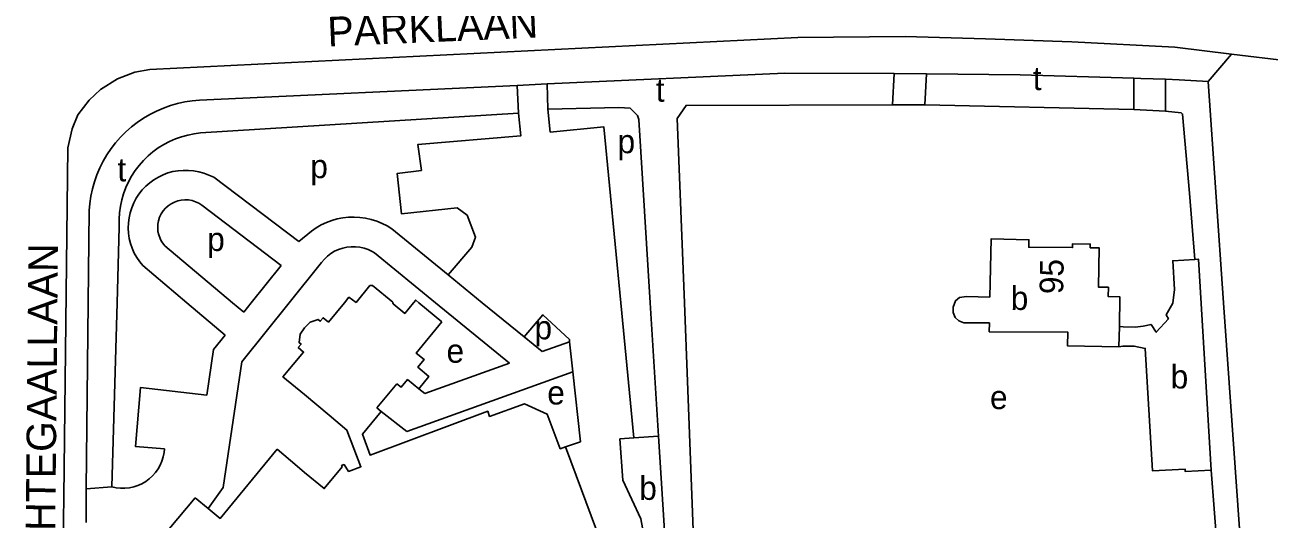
# Model space of a CAD drawing. Extents: x 161775 to 163181, y 382878 to 383925.
# Drawn here: x 161952.7 to 162163.3, y 383537.4 to 383621.1 of the extents above; entities that cross this region are included whole.
import ezdxf

# ---------------------------------------------------------------- set-up
doc = ezdxf.new("R2010")
doc.units = 0
for name, color, linetype in [('BLT_Basislijn', 7, 'Continuous'), ('BLT_Bebouwing', 7, 'Continuous'), ('BLT_Centroide', 7, 'Continuous'), ('BLT_Huisnummer', 7, 'Continuous'), ('BLT_Onderverdeling_panden', 7, 'Continuous'), ('BLT_Straatnaam', 7, 'Continuous')]:
    doc.layers.add(name, color=color, linetype=linetype)

msp = doc.modelspace()

# ---------------------------------------------------------------- linework, layer by layer
at = {"layer": 'BLT_Basislijn'}
for p, q in [((162147.39, 383617.3), (162156.96, 383616.15)), ((162153.03, 383611.52), (162156.96, 383616.15)), ((162099.86, 383612.83), (162099.6, 383607.57)), ((162099.86, 383612.83), (162105.35, 383612.82)), ((162105.02, 383607.53), (162105.35, 383612.82)), ((162140.43, 383612.06), (162140.43, 383606.73)), ((162141.64, 383612.02), (162140.43, 383612.06)), ((162145.81, 383611.88), (162141.64, 383612.02)), ((162145.78, 383606.45), (162145.81, 383611.88)), ((162148.09, 383611.77), (162145.81, 383611.88)), ((162153.03, 383611.52), (162148.09, 383611.77)), ((162036.05, 383610.83), (161982.25, 383608.35)), ((162036.05, 383610.83), (162041.08, 383611.08)), ((162036.24, 383606.12), (162036.05, 383610.83)), ((162041.2, 383606.79), (162041.08, 383611.08)), ((162155.64, 383574.02), (162153.03, 383611.52)), ((162099.6, 383607.57), (162105.02, 383607.53)), ((162140.43, 383606.73), (162105.02, 383607.53)), ((162036.24, 383606.12), (161982.41, 383602.78)), ((162145.78, 383606.45), (162140.43, 383606.73)), ((161984.64, 383595.29), (161999.05, 383584.38)), ((161963.54, 383589.62), (161963.38, 383574.02)), ((161982.62, 383590.54), (161996.09, 383580.35)), ((161968.65, 383586.84), (161968.28, 383574.02)), ((162014.8, 383586.52), (162024.32, 383578.75)), ((161976.36, 383583.66), (161987.85, 383574.02)), ((162011.87, 383582.48), (162022.22, 383574.02)), ((161972.64, 383580.32), (161980.11, 383574.02)), ((161991, 383574.02), (161996.09, 383580.35)), ((162024.32, 383578.75), (162030.11, 383574.02)), ((161963.38, 383574.02), (161963.03, 383542.53)), ((161968.28, 383574.02), (161967.39, 383542.85)), ((161980.11, 383574.02), (161986.6, 383568.55)), ((161987.85, 383574.02), (161989.73, 383572.44)), ((161989.73, 383572.44), (161991, 383574.02)), ((162022.22, 383574.02), (162034.74, 383563.79)), ((162030.11, 383574.02), (162037.19, 383568.24)), ((162161.28, 383493.04), (162155.64, 383574.02)), ((162037.19, 383568.24), (162040.24, 383565.75)), ((162040.24, 383565.75), (162044.91, 383567.43)), ((162044.91, 383567.43), (162045.45, 383562.31)), ((162020.41, 383558.65), (162034.74, 383563.79)), ((162017.32, 383552.23), (162045.45, 383562.31)), ((162019.36, 383559.43), (162020.41, 383558.65)), ((162012.99, 383555.61), (162017.32, 383552.23)), ((162153.52, 383545.68), (162156.18, 383511.56)), ((161963.03, 383542.53), (161963.02, 383536.82)), ((161967.39, 383542.85), (161963.03, 383542.53)), ((161983.68, 383539.17), (161986.22, 383542.73))]:
    msp.add_line(p, q, dxfattribs=at)
for points in [[(161973.85, 383613.54), (162083.56, 383618.94), (162101.7, 383619.1), (162115.33, 383618.75), (162129.91, 383618.23), (162147.39, 383617.3)], [(162156.96, 383616.15), (162166.39, 383615.01), (162177.92, 383614.05)], [(161959.97, 383600.25), (161960.67, 383603.5), (161961.63, 383605.86), (161963.55, 383608.36), (161965.5, 383610.15), (161968.34, 383611.93), (161971.29, 383613.05), (161973.85, 383613.54)], [(162099.86, 383612.83), (162081.33, 383612.9), (162041.08, 383611.08)], [(162105.35, 383612.82), (162121.16, 383612.65), (162140.43, 383612.06)], [(161982.25, 383608.35), (161981, 383608.23), (161979.75, 383608.04), (161978.52, 383607.77), (161977.31, 383607.42), (161976.12, 383607), (161974.96, 383606.5), (161973.84, 383605.93), (161972.75, 383605.29), (161971.71, 383604.58), (161970.71, 383603.81), (161969.77, 383602.97), (161968.88, 383602.08), (161968.04, 383601.13), (161967.27, 383600.13), (161966.57, 383599.09), (161965.93, 383598), (161965.36, 383596.87), (161964.87, 383595.71), (161964.45, 383594.52), (161964.1, 383593.31), (161963.84, 383592.08), (161963.65, 383590.83), (161963.54, 383589.62)], [(162064.33, 383574.02), (162063.14, 383605.21), (162064.62, 383607.45), (162099.6, 383607.57)], [(162036.24, 383606.12), (162036.67, 383602.3), (162019.21, 383600.83), (162019.82, 383596.43), (162015.71, 383595.92), (162016.44, 383589.07), (162025.85, 383590.08), (162027.55, 383588.85), (162028.94, 383585.13), (162028.32, 383583.43), (162024.32, 383578.75)], [(162041.2, 383606.79), (162053.26, 383607.1), (162055.13, 383606.99), (162056.4, 383605.72), (162056.61, 383605.05), (162058.56, 383574.02)], [(162041.2, 383606.79), (162041.62, 383602.92), (162050.69, 383603.83), (162053.55, 383574.02)], [(162145.78, 383606.45), (162148.44, 383606.21), (162148.69, 383605.99), (162149.88, 383592.58), (162150.75, 383581.36)], [(161982.41, 383602.78), (161981.32, 383602.64), (161980.24, 383602.43), (161979.18, 383602.14), (161978.15, 383601.77), (161977.14, 383601.33), (161976.17, 383600.82), (161975.24, 383600.24), (161974.36, 383599.59), (161973.52, 383598.88), (161972.74, 383598.11), (161972.01, 383597.28), (161971.35, 383596.41), (161970.75, 383595.49), (161970.22, 383594.52), (161969.77, 383593.52), (161969.38, 383592.49), (161969.08, 383591.44), (161968.85, 383590.37), (161968.7, 383589.28), (161968.62, 383588.18), (161968.63, 383587.09), (161968.65, 383586.84)], [(161959.97, 383600.25), (161959.24, 383541.16), (161959.19, 383537.22), (161958.93, 383519.07), (161960.13, 383499.52), (161961.78, 383487.14), (161963.57, 383476.99), (161965.01, 383471.01)], [(161984.64, 383595.29), (161982.95, 383595.95), (161982.1, 383596.19), (161981.24, 383596.36), (161980.36, 383596.45), (161979.48, 383596.45), (161978.61, 383596.38), (161977.74, 383596.23), (161976.89, 383596), (161976.07, 383595.7), (161975.27, 383595.32), (161974.52, 383594.86), (161973.81, 383594.35), (161973.14, 383593.77), (161972.54, 383593.13), (161971.99, 383592.44), (161971.51, 383591.71), (161971.1, 383590.93), (161970.76, 383590.12), (161970.49, 383589.28), (161970.3, 383588.42), (161970.2, 383587.55), (161970.17, 383586.67), (161970.22, 383585.79), (161970.35, 383584.92), (161970.56, 383584.07), (161970.84, 383583.24), (161971.2, 383582.43), (161971.63, 383581.67), (161972.13, 383580.94), (161972.64, 383580.32)], [(161982.62, 383590.54), (161982.11, 383590.87), (161981.56, 383591.13), (161980.98, 383591.32), (161980.37, 383591.43), (161979.76, 383591.46), (161979.15, 383591.41), (161978.56, 383591.28), (161977.98, 383591.08), (161977.44, 383590.8), (161976.93, 383590.45), (161976.48, 383590.04), (161976.09, 383589.57), (161975.76, 383589.06), (161975.49, 383588.51), (161975.31, 383587.92), (161975.2, 383587.32), (161975.17, 383586.71), (161975.21, 383586.1), (161975.34, 383585.51), (161975.55, 383584.93), (161975.83, 383584.39), (161976.18, 383583.88), (161976.36, 383583.66)], [(161999.05, 383584.38), (162001.22, 383586.17), (162002.01, 383586.72), (162002.85, 383587.2), (162003.73, 383587.61), (162004.64, 383587.95), (162005.57, 383588.21), (162006.52, 383588.39), (162007.48, 383588.5), (162008.45, 383588.52), (162009.41, 383588.47), (162010.37, 383588.33), (162011.32, 383588.12), (162012.24, 383587.83), (162013.14, 383587.47), (162014, 383587.03), (162014.8, 383586.52)], [(162002.91, 383580.86), (162003.38, 383581.42), (162003.91, 383581.92), (162004.49, 383582.36), (162005.12, 383582.74), (162005.79, 383583.05), (162006.48, 383583.28), (162007.2, 383583.44), (162007.93, 383583.52), (162008.66, 383583.51), (162009.39, 383583.43), (162010.1, 383583.27), (162010.8, 383583.03), (162011.46, 383582.72), (162011.87, 383582.48)], [(161997.41, 383574.02), (162002.91, 383580.86)], [(161986.22, 383542.73), (161989.38, 383564.03), (161997.41, 383574.02)], [(162053.55, 383574.02), (162055.75, 383551.14)], [(162058.56, 383574.02), (162059.98, 383551.43)], [(162066.25, 383523.72), (162064.33, 383574.02)], [(162037.19, 383568.24), (162040.38, 383571.98), (162044.87, 383567.81), (162044.91, 383567.43)], [(161983.48, 383558.35), (161984.63, 383566.11), (161986.6, 383568.55)], [(162045.45, 383562.31), (162046.72, 383550.48), (162044.21, 383549.62)], [(161976.3, 383549.27), (161971.41, 383549.65), (161972.24, 383559.65), (161983.48, 383558.35)], [(161967.39, 383542.85), (161968.12, 383542.69), (161968.87, 383542.6), (161969.62, 383542.6), (161970.36, 383542.68), (161971.1, 383542.83), (161971.81, 383543.06), (161972.49, 383543.37), (161973.14, 383543.74), (161973.74, 383544.19), (161974.3, 383544.69), (161974.79, 383545.26), (161975.22, 383545.87), (161975.59, 383546.52), (161975.88, 383547.21), (161976.1, 383547.93), (161976.24, 383548.66), (161976.3, 383549.27)]]:
    msp.add_lwpolyline(points, dxfattribs=at)
at = {"layer": 'BLT_Bebouwing'}
for p, q in [((162015.66, 383560.31), (162012.29, 383556.21)), ((162004.21, 383554.97), (162000, 383558.46)), ((162012.29, 383556.21), (162012.99, 383555.61)), ((162053.43, 383550.99), (162055.75, 383551.14)), ((162055.75, 383551.14), (162059.98, 383551.43)), ((162059.98, 383551.43), (162061.11, 383532.76)), ((161995.4, 383549.21), (161998.76, 383546.33)), ((161998.76, 383546.33), (162000, 383545.3)), ((161981.51, 383540.97), (161983.68, 383539.17))]:
    msp.add_line(p, q, dxfattribs=at)
for points in [[(162137.98, 383570.02), (162138.07, 383575.02), (162136.11, 383575.06), (162136.14, 383576.64), (162134.44, 383576.67), (162134.58, 383583.32), (162133.05, 383583.35), (162133.06, 383583.95), (162130.06, 383584.01), (162130.05, 383583.36), (162122.65, 383583.41), (162122.68, 383584.69), (162116.25, 383584.83), (162116.03, 383574.99), (162112.11, 383575.08), (162110.92, 383574.93), (162110.26, 383574.35), (162109.86, 383573.26), (162109.85, 383572.36), (162110.19, 383571.55), (162110.82, 383570.97), (162111.63, 383570.62), (162115.99, 383570.6), (162115.96, 383569.12), (162129.27, 383569.04), (162129.22, 383566.72), (162137.91, 383566.56)], [(162150.75, 383581.36), (162147.01, 383581.13), (162147.3, 383576.26), (162147.02, 383573.97), (162145.9, 383571.95), (162146.28, 383571.31), (162144.22, 383569.04), (162143.34, 383570.36), (162142.01, 383570.03), (162140.64, 383569.9), (162138.65, 383569.94), (162137.98, 383570.02)], [(162153.52, 383545.68), (162153.54, 383545.68), (162151.4, 383581.4), (162150.75, 383581.36)], [(162006.77, 383574.02), (162007.53, 383574.95), (162008.75, 383574.08), (162011.09, 383576.92), (162011.52, 383576.95), (162014.97, 383574.1), (162014.98, 383574.02)], [(162000, 383569.75), (162000.95, 383570.74), (162002.33, 383571.19), (162002.67, 383570.9), (162003.16, 383571.49), (162004.06, 383570.74), (162006.77, 383574.02)], [(162014.98, 383574.02), (162015.01, 383573.86), (162016.98, 383572.22), (162018.46, 383574.02)], [(162018.46, 383574.02), (162018.84, 383574.48), (162019.4, 383574.02)], [(162019.4, 383574.02), (162023.28, 383570.81)], [(162000, 383569.75), (161999.26, 383568.72), (161999.09, 383567.29), (161999.44, 383567.02), (161998.96, 383566.45), (161999.85, 383565.68), (161996.36, 383561.48), (162000, 383558.46)], [(162023.28, 383570.81), (162018.91, 383565.5), (162020.29, 383564.41), (162019.21, 383563.11), (162021.07, 383561.52), (162019.36, 383559.43)], [(162137.91, 383566.56), (162138.59, 383566.68), (162140.49, 383566.65), (162142.36, 383566.3), (162143.61, 383545.53), (162149.12, 383545.86), (162149.15, 383545.42), (162153.52, 383545.68)], [(162019.36, 383559.43), (162017.46, 383561), (162016.38, 383559.71), (162015.66, 383560.31)], [(162012.99, 383555.61), (162009.81, 383551.76), (162011.12, 383548.23), (162031.04, 383555.65), (162031.36, 383554.78), (162037.25, 383556.93), (162041.13, 383555.14), (162043.33, 383549.29), (162044.21, 383549.62)], [(162000, 383545.3), (162003.35, 383542.55), (162006.39, 383546.21), (162006.28, 383546.43), (162006.71, 383546.62), (162007.49, 383545.45), (162009.56, 383546.24), (162007.21, 383552.47), (162004.21, 383554.97)], [(162061.11, 383532.76), (162058.27, 383530.46), (162056.98, 383537.43), (162053.91, 383543.98), (162053.43, 383550.99)], [(161983.68, 383539.17), (161985.71, 383537.5), (161995.4, 383549.21)], [(162044.21, 383549.62), (162050.36, 383533.06), (162049.67, 383532.8), (162050.57, 383530.45), (162051.25, 383530.69), (162053.6, 383523.88), (162055.89, 383500.73)], [(161976.23, 383528.42), (161975.66, 383534), (161981.51, 383540.97)]]:
    msp.add_lwpolyline(points, dxfattribs=at)
at = {"layer": 'BLT_Onderverdeling_panden'}
msp.add_line((162137.98, 383570.02), (162137.91, 383566.56), dxfattribs=at)

# ---------------------------------------------------------------- texts
at = {"layer": 'BLT_Centroide'}
for s, p in [('t', (162123.33, 383610.04)), ('t', (162059.49, 383608.07)), ('p', (162053.02, 383599.35)), ('t', (161968.33, 383594.58)), ('p', (162001, 383595.13)), ('p', (161983.54, 383582.79)), ('b', (162119.59, 383572.81)), ('p', (162038.96, 383567.83)), ('e', (162024.06, 383563.86)), ('b', (162146.67, 383559.5)), ('e', (162041.12, 383556.79)), ('e', (162116.08, 383556.01)), ('b', (162056.7, 383540.64))]:
    msp.add_text(s, height=4, dxfattribs=at).set_placement(p)
at = {"layer": 'BLT_Huisnummer'}
msp.add_text('95', height=4, rotation=88.9482, dxfattribs=at).set_placement((162128.46, 383575.45))
at = {"layer": 'BLT_Straatnaam'}
for s, rotation, p in [('PARKLAAN', 2.4537, (162004, 383617.42)), ('NACHTEGAALLAAN', 89.4414, (161957.67, 383521.25))]:
    msp.add_text(s, height=5, rotation=rotation, dxfattribs=at).set_placement(p)

doc.saveas('drawing.dxf')
